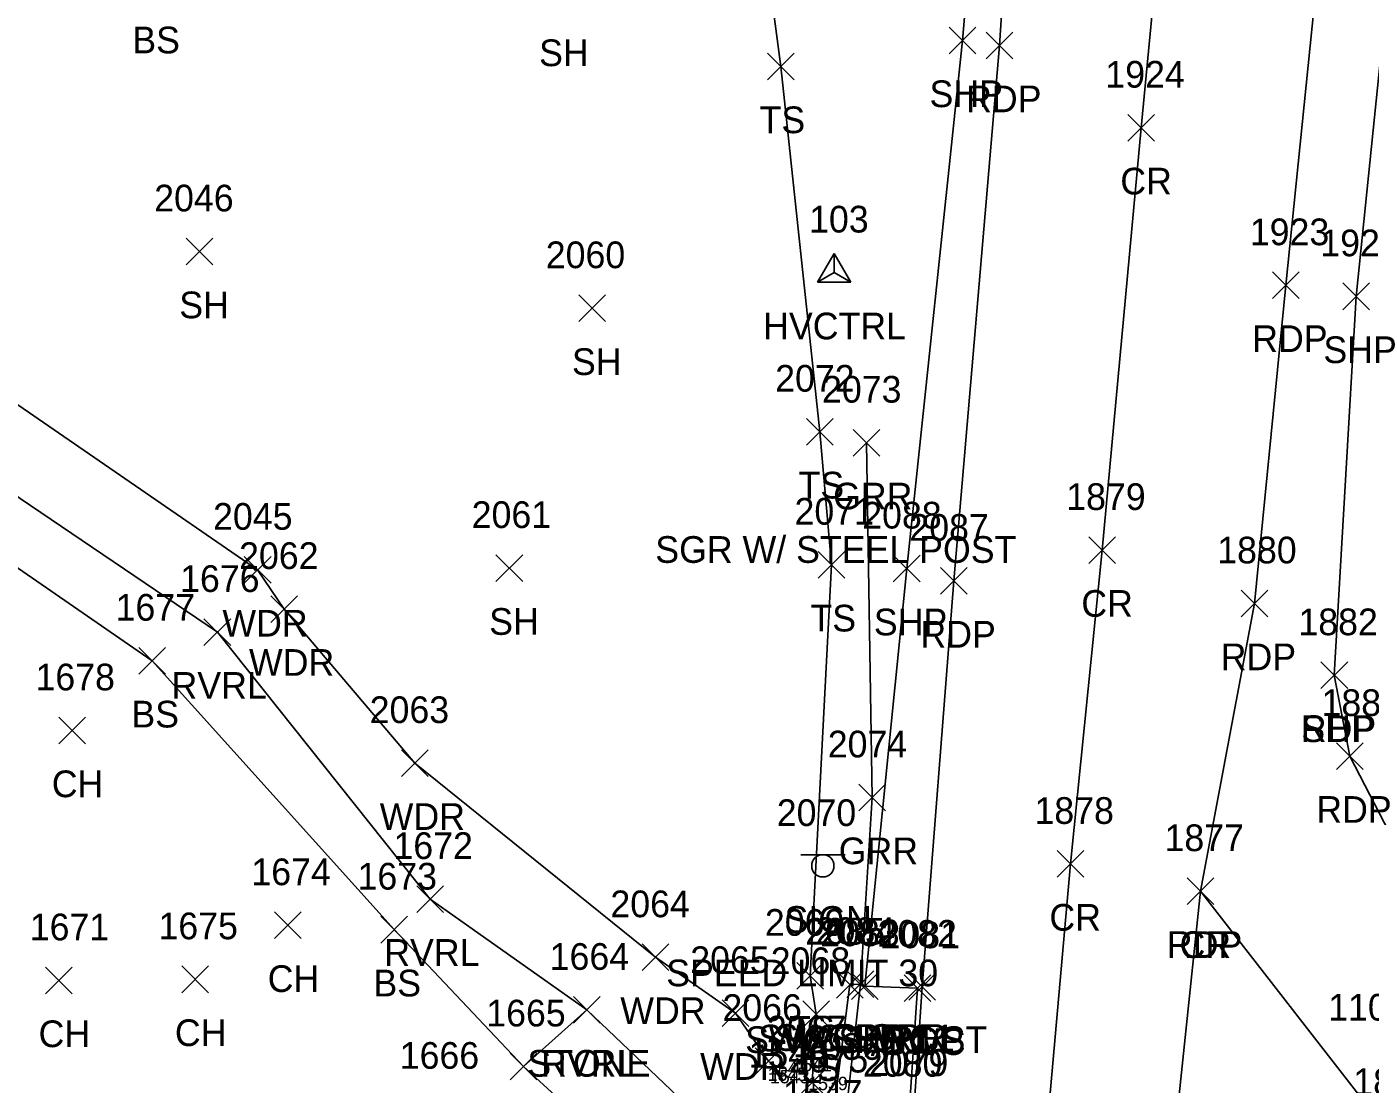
# Model space of a CAD drawing. Extents: x 1653908 to 1654393, y 539913 to 544256.
# Drawn here: x 1653996.5 to 1654097.1, y 541690.6 to 541769.8 of the extents above; entities that cross this region are included whole.
import ezdxf

# ---------------------------------------------------------------- set-up
doc = ezdxf.new("R2010")
doc.units = 0
for name, color, linetype in [('B_I', 7, 'Continuous'), ('C_A', 7, 'Continuous'), ('C_I', 7, 'Continuous'), ('CPSM', 7, 'Continuous'), ('L_A', 7, 'Continuous'), ('L_I', 7, 'Continuous'), ('L_TIC', 7, 'Continuous'), ('LASF', 7, 'Continuous'), ('LAWA', 7, 'Continuous'), ('LAWE', 7, 'Continuous'), ('LELB', 7, 'Continuous'), ('P_A', 7, 'Continuous'), ('P_I', 7, 'Continuous'), ('P_TIC', 7, 'Continuous'), ('PET', 7, 'Continuous'), ('PRC', 7, 'Continuous'), ('PSP', 7, 'Continuous'), ('R_A', 7, 'Continuous'), ('R_C', 7, 'Continuous'), ('R_I', 7, 'Continuous'), ('R_TIC', 7, 'Continuous'), ('RGR', 7, 'Continuous'), ('RSW', 7, 'Continuous'), ('S_A', 7, 'Continuous'), ('S_C', 7, 'Continuous'), ('S_I', 7, 'Continuous'), ('SSGN', 7, 'Continuous'), ('U_I', 7, 'Continuous')]:
    doc.layers.add(name, color=color, linetype=linetype)

msp = doc.modelspace()

# ---------------------------------------------------------------- linework, layer by layer
at = {"layer": 'CPSM'}
for p, q in [((1654055.74, 541750.64), (1654056.99, 541752.81)), ((1654058.24, 541750.64), (1654056.99, 541752.81)), ((1654056.99, 541751.37), (1654056.99, 541752.81)), ((1654055.74, 541750.64), (1654056.99, 541751.37)), ((1654056.99, 541751.37), (1654056.99, 541751.37)), ((1654056.99, 541751.37), (1654058.24, 541750.64)), ((1654055.74, 541750.64), (1654058.24, 541750.64))]:
    msp.add_line(p, q, dxfattribs=at)
at = {"layer": 'L_TIC'}
for points in [[(1654052, 541765.81), (1654054, 541767.81)], [(1654054, 541765.81), (1654052, 541767.81)], [(1654008.47, 541751.95), (1654010.47, 541753.95)], [(1654010.47, 541751.95), (1654008.47, 541753.95)], [(1654037.87, 541747.7), (1654039.87, 541749.7)], [(1654039.87, 541747.7), (1654037.87, 541749.7)], [(1654054.92, 541738.45), (1654056.92, 541740.45)], [(1654056.92, 541738.45), (1654054.92, 541740.45)], [(1654012.82, 541728.11), (1654014.82, 541730.11)], [(1654014.82, 541728.11), (1654012.82, 541730.11)], [(1654031.67, 541728.24), (1654033.67, 541730.24)], [(1654033.67, 541728.24), (1654031.67, 541730.24)], [(1654055.81, 541728.49), (1654057.81, 541730.49)], [(1654057.81, 541728.49), (1654055.81, 541730.49)], [(1654014.81, 541725.17), (1654016.81, 541727.17)], [(1654016.81, 541725.17), (1654014.81, 541727.17)], [(1654009.8, 541723.45), (1654011.8, 541725.45)], [(1654011.8, 541723.45), (1654009.8, 541725.45)], [(1654004.92, 541721.3), (1654006.92, 541723.3)], [(1654006.92, 541721.3), (1654004.92, 541723.3)], [(1653998.92, 541716.08), (1654000.92, 541718.08)], [(1654000.92, 541716.08), (1653998.92, 541718.08)], [(1654024.6, 541713.63), (1654026.6, 541715.63)], [(1654026.6, 541713.63), (1654024.6, 541715.63)], [(1654025.73, 541703.45), (1654027.73, 541705.45)], [(1654027.73, 541703.45), (1654025.73, 541705.45)], [(1654015.09, 541701.49), (1654017.09, 541703.49)], [(1654017.09, 541701.49), (1654015.09, 541703.49)], [(1654023.04, 541701.16), (1654025.04, 541703.16)], [(1654025.04, 541701.16), (1654023.04, 541703.16)], [(1654042.62, 541699.09), (1654044.62, 541701.09)], [(1654044.62, 541699.09), (1654042.62, 541701.09)], [(1653997.93, 541697.36), (1653999.93, 541699.36)], [(1653999.93, 541697.36), (1653997.93, 541699.36)], [(1654008.13, 541697.44), (1654010.13, 541699.44)], [(1654010.13, 541697.44), (1654008.13, 541699.44)], [(1654054.21, 541697.7), (1654056.21, 541699.7)], [(1654056.21, 541697.7), (1654054.21, 541699.7)], [(1654037.47, 541695.15), (1654039.47, 541697.15)], [(1654039.47, 541695.15), (1654037.47, 541697.15)], [(1654037.47, 541695.15), (1654039.47, 541697.15)], [(1654039.47, 541695.15), (1654037.47, 541697.15)], [(1654048.6, 541694.91), (1654050.6, 541696.91)], [(1654050.6, 541694.91), (1654048.6, 541696.91)], [(1654054.64, 541694.83), (1654056.64, 541696.83)], [(1654056.64, 541694.83), (1654054.64, 541696.83)], [(1654032.73, 541690.91), (1654034.73, 541692.91)], [(1654034.73, 541690.91), (1654032.73, 541692.91)], [(1654032.73, 541690.91), (1654034.73, 541692.91)], [(1654034.73, 541690.91), (1654032.73, 541692.91)], [(1654032.73, 541690.91), (1654034.73, 541692.91)], [(1654034.73, 541690.91), (1654032.73, 541692.91)], [(1654051.07, 541691.32), (1654053.07, 541693.32)], [(1654053.07, 541691.32), (1654051.07, 541693.32)], [(1654054.35, 541689.71), (1654056.35, 541691.71)], [(1654056.35, 541689.71), (1654054.35, 541691.71)]]:
    msp.add_lwpolyline(points, dxfattribs=at)
at = {"layer": 'LASF'}
for points in [[(1654038.47, 541696.15), (1654033.73, 541691.91)], [(1654082.44, 541647.34), (1654081.33, 541637.75), (1654062.76, 541655.23), (1654048.06, 541678.77), (1654033.73, 541691.91)]]:
    msp.add_lwpolyline(points, dxfattribs=at)
at = {"layer": 'LAWA'}
msp.add_lwpolyline([(1653943.46, 541776.4), (1653963.43, 541758.85), (1653979.12, 541751.71), (1653991.66, 541744.34), (1654013.82, 541729.11), (1654015.81, 541726.17), (1654025.6, 541714.63), (1654043.62, 541700.09), (1654049.6, 541695.91), (1654052.07, 541692.32)], dxfattribs=at)
at = {"layer": 'LAWE'}
msp.add_lwpolyline([(1654199.26, 541471.36), (1654181.86, 541503.28), (1654178.82, 541509.62), (1654164.46, 541535.09), (1654153.73, 541550.44), (1654126.86, 541584.5), (1654110.11, 541605.8), (1654090.45, 541629.39), (1654082.44, 541647.34), (1654069.57, 541661.67), (1654051.08, 541684.15), (1654038.47, 541696.15), (1654026.73, 541704.45), (1654010.8, 541724.45), (1653979.68, 541745.5), (1653961.84, 541751.35), (1653943.48, 541769.15)], dxfattribs=at)
at = {"layer": 'LELB'}
for points in [[(1654055.35, 541690.71), (1654055.64, 541695.83), (1654055.21, 541698.7), (1654056.81, 541729.49), (1654055.92, 541739.45), (1654053, 541766.81), (1654049.68, 541791.82), (1654058.67, 541796.23), (1654049.5, 541797.39)], [(1654033.73, 541691.91), (1654024.04, 541702.16), (1654005.92, 541722.3), (1653978.92, 541740.92), (1653958.09, 541748.83), (1653942.72, 541767.95)]]:
    msp.add_lwpolyline(points, dxfattribs=at)
at = {"layer": 'P_TIC'}
for points in [[(1654065.61, 541767.76), (1654067.61, 541769.76)], [(1654067.61, 541767.76), (1654065.61, 541769.76)], [(1654068.39, 541767.38), (1654070.39, 541769.38)], [(1654070.39, 541767.38), (1654068.39, 541769.38)], [(1654079, 541761.22), (1654081, 541763.22)], [(1654081, 541761.22), (1654079, 541763.22)], [(1654089.82, 541749.42), (1654091.82, 541751.42)], [(1654091.82, 541749.42), (1654089.82, 541751.42)], [(1654095.1, 541748.59), (1654097.1, 541750.59)], [(1654097.1, 541748.59), (1654095.1, 541750.59)], [(1654076.08, 541729.59), (1654078.08, 541731.59)], [(1654078.08, 541729.59), (1654076.08, 541731.59)], [(1654061.43, 541728.2), (1654063.43, 541730.2)], [(1654063.43, 541728.2), (1654061.43, 541730.2)], [(1654064.97, 541727.28), (1654066.97, 541729.28)], [(1654066.97, 541727.28), (1654064.97, 541729.28)], [(1654087.47, 541725.59), (1654089.47, 541727.59)], [(1654089.47, 541725.59), (1654087.47, 541727.59)], [(1654093.46, 541720.21), (1654095.46, 541722.21)], [(1654095.46, 541720.21), (1654093.46, 541722.21)], [(1654093.46, 541720.21), (1654095.46, 541722.21)], [(1654095.46, 541720.21), (1654093.46, 541722.21)], [(1654094.63, 541714.16), (1654096.63, 541716.16)], [(1654096.63, 541714.16), (1654094.63, 541716.16)], [(1654073.69, 541706.08), (1654075.69, 541708.08)], [(1654075.69, 541706.08), (1654073.69, 541708.08)], [(1654083.43, 541704.04), (1654085.43, 541706.04)], [(1654085.43, 541704.04), (1654083.43, 541706.04)], [(1654083.43, 541704.04), (1654085.43, 541706.04)], [(1654085.43, 541704.04), (1654083.43, 541706.04)], [(1654058.29, 541696.92), (1654060.29, 541698.92)], [(1654060.29, 541696.92), (1654058.29, 541698.92)], [(1654062.58, 541696.88), (1654064.58, 541698.88)], [(1654064.58, 541696.88), (1654062.58, 541698.88)]]:
    msp.add_lwpolyline(points, dxfattribs=at)
at = {"layer": 'PET'}
for points in [[(1654079.78, 541659.55), (1654071.38, 541669.62), (1654062.1, 541680.77), (1654062.28, 541682.13), (1654062.95, 541688.2), (1654063.58, 541697.88), (1654065.97, 541728.28), (1654069.39, 541768.38), (1654071.19, 541795.88), (1654073.5, 541821.5), (1654077.02, 541859.14), (1654082.16, 541914.04), (1654084.92, 541947.88), (1654085.88, 541956.64), (1654088.37, 541984.8), (1654091.95, 542029.61), (1654095.3, 542063.75), (1654100.14, 542114.45), (1654103.13, 542154.15), (1654108.14, 542200.44), (1654110.74, 542235.38)], [(1654079.78, 541659.55), (1654080.09, 541663.58), (1654084.43, 541705.04), (1654088.47, 541726.59), (1654090.82, 541750.42), (1654095.24, 541793.92), (1654098.73, 541834.91), (1654102.67, 541873.55), (1654106.19, 541915.36), (1654108.8, 541937.78), (1654112.78, 541976.54), (1654113.71, 541994.76), (1654118.51, 542040.26), (1654122.37, 542081.46), (1654125.51, 542120.57), (1654128.86, 542154.49), (1654132.07, 542197.52), (1654136.39, 542232.74)], [(1654080.09, 541663.58), (1654083.55, 541666.57), (1654088.66, 541667.17), (1654094.47, 541664.84), (1654099.96, 541660.14), (1654111.9, 541663.59), (1654122.03, 541667.7), (1654105.28, 541696.47), (1654095.63, 541715.16), (1654094.46, 541721.21)]]:
    msp.add_lwpolyline(points, dxfattribs=at)
at = {"layer": 'PRC'}
for points in [[(1654071.38, 541669.62), (1654074.69, 541707.08), (1654077.08, 541730.59), (1654080, 541762.22), (1654083.13, 541795.12), (1654087.25, 541836.36), (1654090.63, 541873.54), (1654094.48, 541915.81), (1654096.59, 541938.82), (1654100.21, 541977.67), (1654102.08, 541996.31), (1654106.33, 542040.19), (1654109.98, 542082.61), (1654113.75, 542122.62), (1654117.05, 542159.88), (1654120.87, 542199.28), (1654124.05, 542234.04)], [(1654225.01, 541487.06), (1654204.16, 541517.09), (1654180.22, 541550.99), (1654156.18, 541588.24), (1654139.45, 541615.76), (1654117.3, 541653.68), (1654111.9, 541663.59), (1654098.63, 541686.77), (1654084.43, 541705.04)]]:
    msp.add_lwpolyline(points, dxfattribs=at)
at = {"layer": 'PSP'}
for points in [[(1654094.46, 541721.21), (1654096.1, 541749.59), (1654101.26, 541800.15), (1654104.96, 541834.32), (1654108.51, 541872.88), (1654110.15, 541890.73), (1654111.77, 541915.01), (1654113.74, 541937.09), (1654116.46, 541969.54), (1654117.65, 541994.22), (1654121.74, 542040.28), (1654126.76, 542081.18), (1654129.73, 542120.03), (1654133.66, 542152.74), (1654138.06, 542196.4), (1654141.28, 542231.97)], [(1654059.29, 541697.92), (1654062.43, 541729.2), (1654066.61, 541768.76), (1654068.98, 541796.43), (1654071.26, 541821.84), (1654073.12, 541859.77), (1654076.97, 541914.97), (1654078.39, 541941.54)]]:
    msp.add_lwpolyline(points, dxfattribs=at)
at = {"layer": 'R_TIC'}
for points in [[(1654058.43, 541737.63), (1654060.43, 541739.63)], [(1654060.43, 541737.63), (1654058.43, 541739.63)], [(1654058.85, 541711.06), (1654060.85, 541713.06)], [(1654060.85, 541711.06), (1654058.85, 541713.06)], [(1654057.18, 541697.04), (1654059.18, 541699.04)], [(1654059.18, 541697.04), (1654057.18, 541699.04)], [(1654057.18, 541697.04), (1654059.18, 541699.04)], [(1654059.18, 541697.04), (1654057.18, 541699.04)], [(1654057.96, 541697.08), (1654059.96, 541699.08)], [(1654059.96, 541697.08), (1654057.96, 541699.08)], [(1654057.96, 541697.08), (1654059.96, 541699.08)], [(1654059.96, 541697.08), (1654057.96, 541699.08)], [(1654058.29, 541696.92), (1654060.29, 541698.92)], [(1654060.29, 541696.92), (1654058.29, 541698.92)], [(1654062.24, 541696.77), (1654064.24, 541698.77)], [(1654064.24, 541696.77), (1654062.24, 541698.77)]]:
    msp.add_lwpolyline(points, dxfattribs=at)
at = {"layer": 'RGR'}
msp.add_lwpolyline([(1654059.43, 541738.63), (1654059.85, 541712.06), (1654058.96, 541698.08), (1654057.99, 541689.41)], dxfattribs=at)
at = {"layer": 'RSW'}
for points in [[(1654056.94, 541688.46), (1654062.21, 541682.34), (1654062.58, 541688.15), (1654063.24, 541697.77), (1654059.29, 541697.92), (1654058.96, 541698.08), (1654058.18, 541698.04)], [(1654056.94, 541688.46), (1654058.18, 541698.04)]]:
    msp.add_lwpolyline(points, dxfattribs=at)
at = {"layer": 'SSGN'}
for p, q in [((1654054.5, 541707.77), (1654057.83, 541707.77)), ((1654056.15, 541706.94), (1654056.15, 541706.94))]:
    msp.add_line(p, q, dxfattribs=at)
msp.add_circle((1654056.15, 541706.94), 0.833, dxfattribs=at)

# ---------------------------------------------------------------- texts
at = {"layer": 'B_I'}
for s, p in [('1545', (1654052.01, 541690.83)), ('1542', (1654052.03, 541691.3)), ('1541', (1654053.86, 541691.55)), ('1543', (1654052.18, 541690.65)), ('1539', (1654055.05, 541690.14))]:
    msp.add_text(s, height=1, dxfattribs=at).set_placement(p)
at = {"layer": 'C_A'}
msp.add_text('HVCTRL', height=2, dxfattribs=at).set_placement((1654051.68, 541746.37))
at = {"layer": 'C_I'}
msp.add_text('103', height=2, dxfattribs=at).set_placement((1654055.12, 541754.37))
at = {"layer": 'L_A'}
for s, p in [('BS', (1654004.43, 541767.79)), ('SH', (1654034.9, 541766.83)), ('TS', (1654051.41, 541761.81)), ('SH', (1654007.95, 541747.95)), ('SH', (1654037.36, 541743.7)), ('TS', (1654054.33, 541734.45)), ('WDR', (1654011.18, 541724.11)), ('SH', (1654031.16, 541724.24)), ('TS', (1654055.22, 541724.49)), ('WDR', (1654013.17, 541721.17)), ('RVRL', (1654007.37, 541719.45)), ('BS', (1654004.36, 541717.3)), ('CH', (1653998.4, 541712.08)), ('WDR', (1654022.96, 541709.63)), ('RVRL', (1654023.3, 541699.45)), ('CH', (1654014.57, 541697.49)), ('BS', (1654022.49, 541697.16)), ('WDR', (1654040.98, 541695.09)), ('CH', (1653997.41, 541693.36)), ('CH', (1654007.62, 541693.44)), ('TS', (1654053.62, 541693.7)), ('STONE', (1654034.02, 541691.15)), ('RVRL', (1654035.04, 541691.15)), ('WDR', (1654046.96, 541690.91)), ('TS', (1654054.05, 541690.83))]:
    msp.add_text(s, height=2, dxfattribs=at).set_placement(p)
at = {"layer": 'L_I'}
for s, p in [('2046', (1654006.07, 541755.95)), ('2060', (1654035.4, 541751.7)), ('2072', (1654052.58, 541742.45)), ('2045', (1654010.48, 541732.11)), ('2061', (1654029.85, 541732.24)), ('2071', (1654054.03, 541732.49)), ('2062', (1654012.43, 541729.17)), ('1676', (1654008.01, 541727.45)), ('1677', (1654003.18, 541725.3)), ('1678', (1653997.18, 541720.08)), ('2063', (1654022.21, 541717.63)), ('1672', (1654023.99, 541707.45)), ('1674', (1654013.35, 541705.49)), ('1673', (1654021.3, 541705.16)), ('2064', (1654040.24, 541703.09)), ('1671', (1653996.75, 541701.36)), ('1675', (1654006.39, 541701.44)), ('2069', (1654051.81, 541701.7)), ('1664', (1654035.69, 541699.15)), ('1664', (1654035.69, 541699.15)), ('2065', (1654046.22, 541698.91)), ('2068', (1654052.25, 541698.83)), ('1665', (1654030.94, 541694.91)), ('1665', (1654030.94, 541694.91)), ('1665', (1654030.94, 541694.91)), ('2066', (1654048.63, 541695.32)), ('2067', (1654051.96, 541693.71)), ('1666', (1654024.46, 541691.74))]:
    msp.add_text(s, height=2, dxfattribs=at).set_placement(p)
at = {"layer": 'P_A'}
for s, p in [('SHP', (1654064.14, 541763.76)), ('RDP', (1654066.88, 541763.38)), ('CR', (1654078.43, 541757.22)), ('RDP', (1654088.31, 541745.42)), ('SHP', (1654093.64, 541744.59)), ('CR', (1654075.51, 541725.59)), ('SHP', (1654059.97, 541724.2)), ('RDP', (1654063.46, 541723.28)), ('RDP', (1654085.95, 541721.59)), ('SHP', (1654091.99, 541716.21)), ('RDP', (1654091.95, 541716.21)), ('RDP', (1654093.11, 541710.16)), ('CR', (1654073.12, 541702.08)), ('RDP', (1654081.92, 541700.04)), ('CR', (1654082.87, 541700.04)), ('SHP', (1654056.82, 541692.92)), ('RDP', (1654061.07, 541692.88))]:
    msp.add_text(s, height=2, dxfattribs=at).set_placement(p)
at = {"layer": 'P_I'}
for s, p in [('1924', (1654077.31, 541765.22)), ('1923', (1654088.13, 541753.42)), ('1922', (1654093.41, 541752.59)), ('1879', (1654074.38, 541733.59)), ('2088', (1654059.1, 541732.2)), ('2087', (1654062.63, 541731.28)), ('1880', (1654085.69, 541729.59)), ('1882', (1654091.77, 541724.21)), ('1882', (1654091.77, 541724.21)), ('1881', (1654093.5, 541718.16)), ('1878', (1654072, 541710.08)), ('1877', (1654081.74, 541708.04)), ('1877', (1654081.74, 541708.04)), ('2083', (1654055.95, 541700.92)), ('2082', (1654060.24, 541700.88)), ('2079', (1654059.6, 541691.2)), ('1876', (1654095.88, 541689.77))]:
    msp.add_text(s, height=2, dxfattribs=at).set_placement(p)
at = {"layer": 'R_A'}
for s, p in [('GRR', (1654056.92, 541733.63)), ('GRR', (1654057.34, 541707.06)), ('SWC SHP1 ST', (1654050.33, 541692.92)), ('SWC SWC1', (1654051.31, 541693.04)), ('SWC SWC1', (1654051.31, 541693.04)), ('SWC GRR', (1654052.54, 541693.08)), ('GRR', (1654056.44, 541693.08)), ('SWC', (1654060.6, 541692.77))]:
    msp.add_text(s, height=2, dxfattribs=at).set_placement(p)
at = {"layer": 'R_C'}
msp.add_text('SGR W/ STEEL POST', height=2, dxfattribs=at).set_placement((1654043.6, 541729.63))
at = {"layer": 'R_I'}
for s, p in [('2073', (1654056.09, 541741.63)), ('2074', (1654056.52, 541715.06)), ('2085', (1654054.84, 541701.04)), ('2085', (1654054.84, 541701.04)), ('2084', (1654055.62, 541701.08)), ('2084', (1654055.62, 541701.08)), ('2083', (1654055.95, 541700.92)), ('2081', (1654060.47, 541700.77)), ('2086', (1654054.6, 541692.41)), ('2075', (1654053.6, 541691.46)), ('2075', (1654053.6, 541691.46)), ('2080', (1654059.15, 541691.15))]:
    msp.add_text(s, height=2, dxfattribs=at).set_placement(p)
at = {"layer": 'S_A'}
msp.add_text('SIGN', height=2, dxfattribs=at).set_placement((1654053.28, 541701.92))
at = {"layer": 'S_C'}
for s, p in [('SPEED LIMIT 30', (1654044.42, 541697.92)), ('1100/0904/0278', (1654094, 541695.35))]:
    msp.add_text(s, height=2, dxfattribs=at).set_placement(p)
at = {"layer": 'S_I'}
msp.add_text('2070', height=2, dxfattribs=at).set_placement((1654052.7, 541709.92))
at = {"layer": 'U_I'}
for s, p in [('1546', (1654050.58, 541691.82)), ('1547', (1654053.16, 541688.89))]:
    msp.add_text(s, height=2, dxfattribs=at).set_placement(p)

doc.saveas('drawing.dxf')
